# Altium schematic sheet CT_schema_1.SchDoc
size 463 x 258 mm
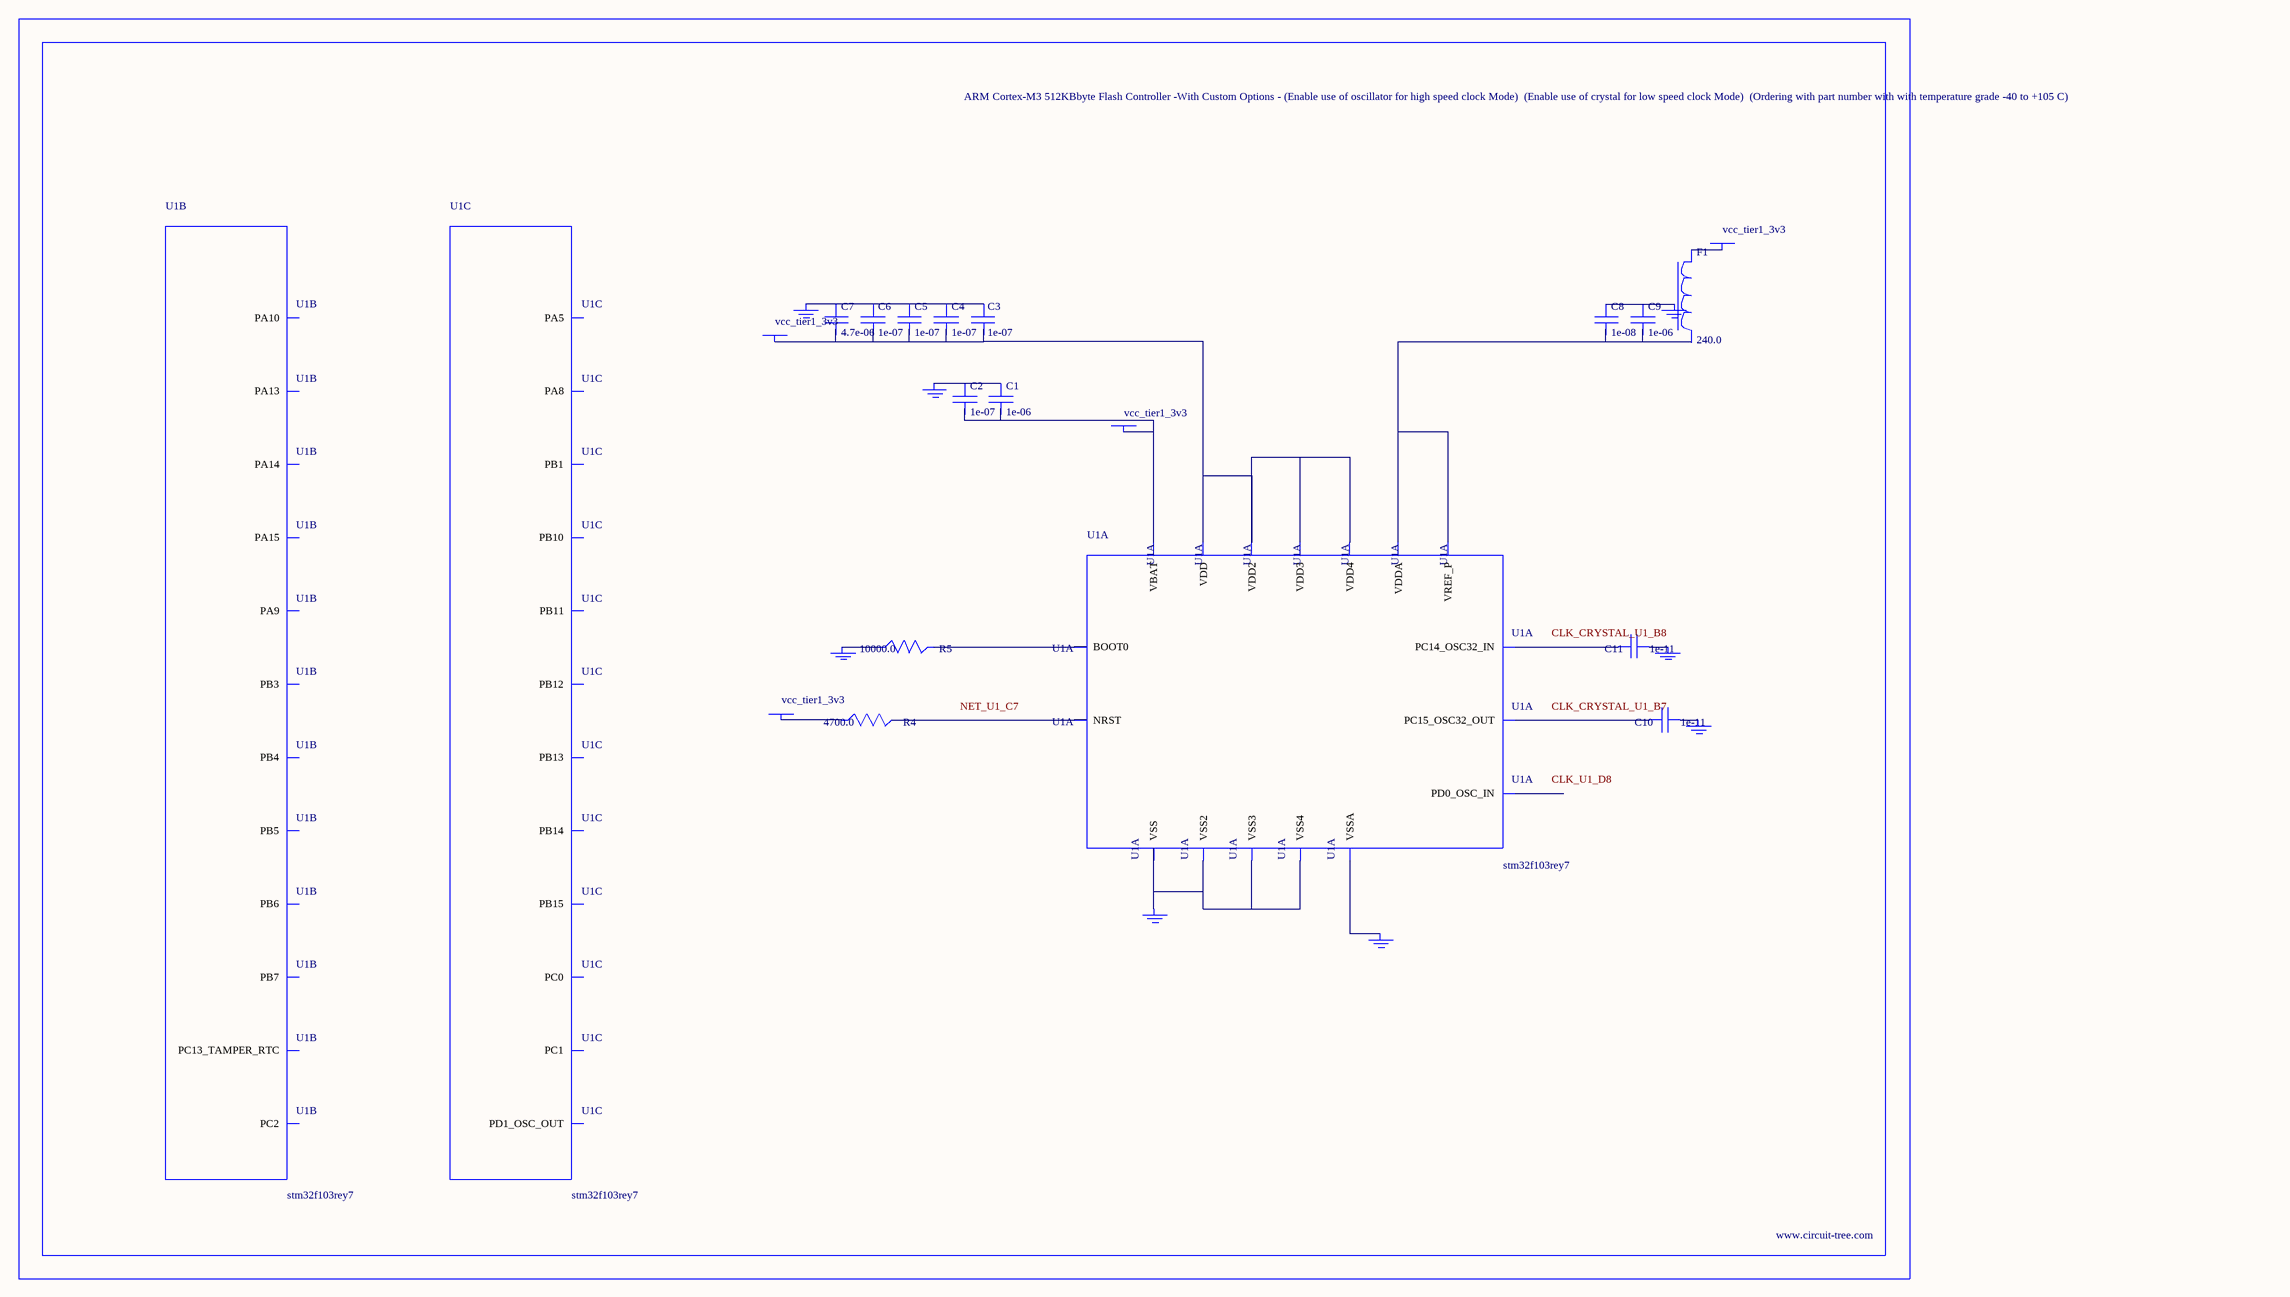
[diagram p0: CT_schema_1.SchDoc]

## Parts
BORDER0  (no value)
C1  1e-06  [C0603]
C2  1e-07  [C0603]
C3  1e-07  [C0603]
C4  1e-07  [C0603]
C5  1e-07  [C0603]
C6  1e-07  [C0603]
C7  4.7e-06  [C0603]
C8  1e-08  [C0603]
C9  1e-06  [C0603]
C10  1e-11  [C0402]
C11  1e-11  [C0402]
F1  240.0  [L0603]
GND_INSTANCE_0_0  (no value)
GND_INSTANCE_0_1  (no value)
GND_INSTANCE_0_2  (no value)
GND_INSTANCE_0_3  (no value)
GND_INSTANCE_0_4  (no value)
GND_INSTANCE_0_5  (no value)
GND_INSTANCE_0_6  (no value)
GND_INSTANCE_0_7  (no value)
POWER_INSTANCE_0_0  vcc_tier1_3v3
POWER_INSTANCE_0_1  vcc_tier1_3v3
POWER_INSTANCE_0_2  vcc_tier1_3v3
POWER_INSTANCE_0_3  vcc_tier1_3v3
R4  4700.0  [R0603]
R5  10000.0  [R0603]
U1  stm32f103rey7  [WLCSP64]  (parts A,B,C of 6)

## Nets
NetC1_1: C1.1 C2.1 GND_INSTANCE_0_0.0(GND)
NetC1_2: C1.2 C2.2 POWER_INSTANCE_0_0.0(PWR) U1.C6(VBAT)
NetC3_1: C3.1 C4.1 C5.1 C6.1 C7.1 GND_INSTANCE_0_2.0(GND)
NetC3_2: C3.2 C4.2 C5.2 C6.2 C7.2 POWER_INSTANCE_0_2.0(PWR) U1.A1(VDD) U1.A8(VDD2) U1.G6(VDD3) U1.H1(VDD4)
NetC8_1: C8.1 C9.1 GND_INSTANCE_0_1.0(GND)
NetC8_2: C8.2 C9.2 U1.F7(VREF_P) U1.G8(VDDA)
NetC10_1: C10.1 GND_INSTANCE_0_4.0(GND)
NetC10_2: C10.2 U1.B7(PC15_OSC32_OUT)
NetC11_1: C11.1 GND_INSTANCE_0_5.0(GND)
NetC11_2: C11.2 U1.B8(PC14_OSC32_IN)
NetF1_1: F1.1 POWER_INSTANCE_0_1.0(PWR)
NetGND_INSTANCE_0_3_0: GND_INSTANCE_0_3.0(GND) R5.1
NetGND_INSTANCE_0_6_0: GND_INSTANCE_0_6.0(GND) U1.E7(VSSA)
NetGND_INSTANCE_0_7_0: GND_INSTANCE_0_7.0(GND) U1.A7(VSS) U1.B1(VSS2) U1.F5(VSS3) U1.H2(VSS4)
NetPOWER_INSTANCE_0_3_0: POWER_INSTANCE_0_3.0(PWR) R4.1
NetR4_2: R4.2 U1.C7(NRST)
NetR5_2: R5.2 U1.A6(BOOT0)

Not connected (* = marked no-connect by the designer): F1 2; U1 A4(PB3) A5(PB5) B2(PA14) B4(PB4) B5(PB6) C3(PA15) C5(PB7) C8(PC13_TAMPER_RTC) D2(PA9) D3(PA10) D4(PA13) D6(PC2) D7(PD1_OSC_OUT) D8(PD0_OSC_IN) E4(PA8) E5(PA5) E8(PC0) F1(PB15) F2(PB14) F3(PB11) F4(PB1) F8(PC1) G1(PB13) G2(PB12) G3(PB10)

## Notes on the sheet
- Labels drawn without touching a wire or pin: CLK_CRYSTAL_U1_B7, CLK_CRYSTAL_U1_B8, CLK_U1_D8, NET_U1_C7

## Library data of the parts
BORDER0 = BORDER_PAGE0
C1 C9 = C0603C105K3RACTU
C2-C6 = 06035C104K4Z2A
C7 = GRM188R6YA475KE15D
C8 = 06035C103K4Z2A
C10 C11 = C0402C100K3GACTU
F1 = Z0603C241ASMST
GND_INSTANCE_0_0-GND_INSTANCE_0_7 = GND
POWER_INSTANCE_0_0-POWER_INSTANCE_0_3 = PWR
R4 = RC0603JR-074K7L
R5 = RC0603JR-0710KL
